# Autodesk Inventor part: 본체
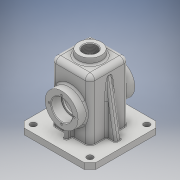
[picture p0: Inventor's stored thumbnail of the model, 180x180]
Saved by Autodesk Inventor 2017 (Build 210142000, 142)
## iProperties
Part Number: 본체
Material: 일반
Document SubType Name: Modeling
Designer: 20
Density: 1 g/cm^3
Appearance: 기본값
Author: 20
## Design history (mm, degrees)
sketch "스케치1"
  geometry: L1 (-32.5, -50)-(32.5, -50); L2 (32.5, -50)-(32.5, 50); L3 (32.5, 50)-(-32.5, 50); L4 (-32.5, 50)-(-32.5, -50); L5 (-32.5, -50)-(32.5, 50); L6 (32.5, -50)-(-32.5, 50); 1 further point
  constraints: 12 end point, 2 midpoint, 2 parallel, 1 horizontal, 1 perpendicular
  dimensions: "d0" = 65 distance of L3.end L2.end; "d1" = 100 distance of L2.end L1.end
extrude "돌출1" new body sketch "스케치1" stored distance "d2" = 65; taper "d3" = 0 deg
sketch "스케치2"
  geometry: L1 (60, -5)-(5, -5); L2 (5, -5)-(5, -60); L3 (5, -60)-(60, -60); L4 (60, -60)-(60, -5); L5 (60, -5)-(5, -60); L6 (5, -5)-(60, -60); 1 further point
  constraints: 12 end point, 2 midpoint, 2 parallel, 1 horizontal, 1 perpendicular
  dimensions: "d4" = 55 distance of L3.end L2.end; "d5" = 55 distance of L2.end L1.end
extrude "돌출2" cut sketch "스케치2" distance "d6" = 95; taper "d7" = 0 deg
sketch "스케치3"
  geometry: L1 (92.5, 27.5)-(-27.5, 27.5); L2 (-27.5, 27.5)-(-27.5, -92.5); L3 (-27.5, -92.5)-(92.5, -92.5); L4 (92.5, -92.5)-(92.5, 27.5); L5 (92.5, 27.5)-(-27.5, -92.5); L6 (-27.5, 27.5)-(92.5, -92.5); L7 (5, -60)-(5, -5) reference; L8 (60, -60)-(5, -60) reference; L9 (60, -5)-(60, -60) reference; L10 (5, -5)-(60, -5) reference; 1 further point
  constraints: 12 end point, 2 midpoint, 2 parallel, 1 horizontal, 1 perpendicular
  dimensions: "d8" = 120 distance of L3.end L2.end; "d9" = 120 distance of L2.end L1.end
extrude "돌출3" join sketch "스케치3" distance "d10" = 10; taper "d11" = 0 deg
sketch "스케치5"
  geometry: L1 (60, -60)-(-60, -60) reference; C1 r 27.5 at (0, -5); 1 further point
  constraints: 1 centre point, 1 vertical alignment
  dimensions: "d12" = 55 diameter of C1; "d13" = 55 distance from line of L1 C1.centre
extrude "돌출4" join sketch "스케치5" distance "d14" = 15; taper "d15" = 0 deg
hole "구멍1" diameter "d19" = 30; stored, may be unused: countersink angle "d23" = 90 deg, drill point angle "d25" = 0 deg; dims "d17" = 10, "d18" = 10, "d20" = 6, "d21" = 35, "d22" = 17, "d24" = 30
sketch "스케치7"
  geometry: C1 r 17.5 at (0, 0) reference; 2 further points
  constraints: 1 vertical alignment
  dimensions: "d26" = 21 distance of C1.centre point (0, 21)
hole "구멍2" sketch "스케치7" at (0, 21) diameter "d27" = 3.242; stored, may be unused: countersink angle "d31" = 90 deg, drill point angle "d33" = 118 deg; dims "d28" = 8, "d29" = 19.05, "d30" = 4.775, "d32" = 10
sketch "스케치8"
  geometry: C1 r 20 at (32.5, -32.5); 1 further point
  constraints: 1 centre point, 1 coincident
  dimensions: "d37" = 40 diameter of C1
extrude "돌출5" join sketch "스케치8" distance "d38" = 10; taper "d39" = 0 deg
feature "면 기울기1" dims angle "d40" = 5 deg
hole "구멍3" diameter "d43" = 22.835; stored, may be unused: countersink angle "d47" = 90 deg, drill point angle "d49" = 0 deg; dims "d41" = 10, "d42" = 10, "d44" = 50, "d45" = 4, "d46" = 2, "d48" = 30
fillet "모깎기1" dims "d50" = 8
fillet "모깎기2" dims "d51" = 3
fillet "모깎기3" dims "d52" = 3
chamfer "모따기1" distance "d54" = 1; stored, may be unused: second distance "d55" = 2, angle "d56" = 45 deg
sketch "스케치9"
  geometry: L1 (48, -50)-(42.522, -18.936); L2 (60, -50)-(60, -60) reference; L3 (60, -50)-(-60, -50) reference; 1 further point
  constraints: 2 end point, 1 point on line
  dimensions: "d57" = 10 deg angle of L2 L1; "d58" = 12 distance of L2.start L1.start; "d59" = 31.06445 vertical distance of L1.start L1.end
feature "리브1" sketch "스케치9" dims "d60" = 1, "d61" = 10, "d62" = 0, "d63" = 0, "d64" = 1, "d65" = 1
fillet "모깎기5" dims "d66" = 3
fillet "모깎기6" dims "d67" = 3
sketch "스케치11"
  geometry: L1 (-57, -65)-(-8, -65) reference; L2 (-57, -60)-(-8, -60) reference; L3 (-35.5, -60)-(-29.5, -60); L4 (-29.5, -60)-(-29.5, -75); L5 (-29.5, -75)-(-35.5, -75); L6 (-35.5, -75)-(-35.5, -60); 2 further points
  constraints: 8 end point, 2 midpoint, 2 parallel, 1 horizontal, 1 perpendicular
  dimensions: "d69" = 6 distance of L4.end L5.end; "d70" = 15 distance of L5.end L3.start
extrude "돌출6" join sketch "스케치11" distance "d71" = 20; taper "d72" = 0 deg
fillet "모깎기7" dims "d73" = 3
fillet "모깎기8" dims "d74" = 3
fillet "모깎기13" dims "d79" = 3
fillet "모깎기14" dims "d80" = 3
chamfer "모따기2" distance "d82" = 10; stored, may be unused: second distance "d83" = 2, angle "d84" = 45 deg
sketch "스케치12"
  geometry: C1 r 5 at (-15, -80); 1 further point
  constraints: 1 centre point
  dimensions: "d86" = 10 diameter of C1; "d87" = 47.5 horizontal distance of C1.centre point (32.5, -32.5); "d88" = 47.5 horizontal distance of point (32.5, -32.5) C1.centre
extrude "돌출7" cut sketch "스케치12" distance "d89" = 15; taper "d90" = 0 deg
node "작업 평면2"
sketch "스케치13"
  geometry: L1 (-19.125, -60)-(19.125, -60) reference; L2 (32.5, -42)-(32.5, 50) reference; 2 further points
  constraints: 1 other
  dimensions: "d98" = 26 distance from line of point (0, -34) L1; "d99" = 32.5 distance from line of L2 point (0, -34)
feature "엠보싱1" sketch "스케치13" dims "d100" = 0.5, "d101" = 0
fillet "모깎기15" dims "d102" = 1
chamfer "모따기3" distance "d103" = 1; stored, may be unused: second distance "d104" = 2, angle "d105" = 45 deg
fillet "모깎기16" dims "d106" = 0.3
node "솔리드1"
mirror "미러1"
mirror "미러2"
pattern_circular "원형 패턴1" dims angle "d35" = 360 deg
mirror "미러3"
mirror "미러4"
mirror "미러5"
pattern_linear "직사각형 패턴1" dims "d93" = 95, "d96" = 95
node "작업 평면1"
other parameters: "d97" = 13
